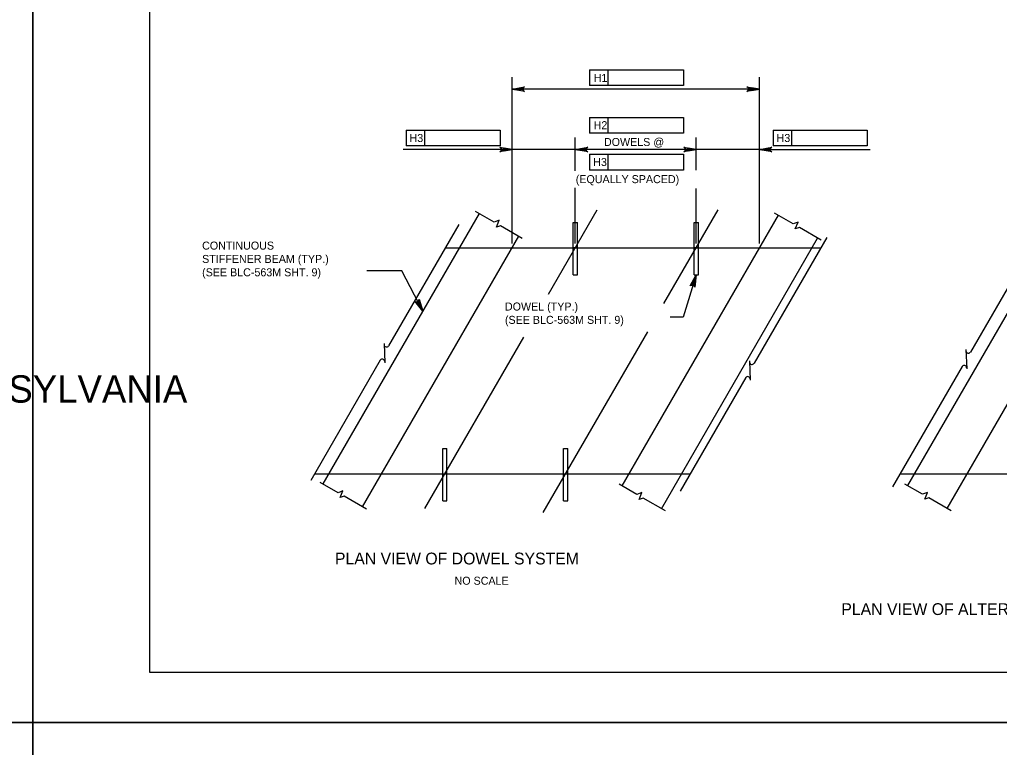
# Model space of a CAD drawing. Extents: x -8 to 75, y -110 to 0.
# Drawn here: x 33.8 to 48.5, y -22.38 to -11.47 of the extents above; entities that cross this region are included whole.
import ezdxf

# ---------------------------------------------------------------- set-up
doc = ezdxf.new("R2010")
doc.units = 0
for name, color, linetype in [('1', 7, 'Continuous'), ('2', 7, 'Continuous'), ('3', 7, 'Continuous'), ('4', 7, 'Continuous'), ('62', 7, 'Continuous'), ('63', 7, 'Continuous')]:
    doc.layers.add(name, color=color, linetype=linetype)

# ---------------------------------------------------------------- blocks, each defined once
blk = doc.blocks.new('D')
at = {"layer": '3'}
for p, q in [((-0.324, 0.383), (-0.383, 0.324)), ((0.349, -0.408), (-0.383, 0.324)), ((0.408, -0.349), (-0.324, 0.383)), ((0.408, -0.349), (0.349, -0.408))]:
    blk.add_line(p, q, dxfattribs=at)

msp = doc.modelspace()

# ---------------------------------------------------------------- linework, layer by layer
at = {"layer": '1'}
msp.add_lwpolyline([(35.75, -21.25), (67.25, -21.25), (67.25, -0.75), (35.75, -0.75)], close=True, dxfattribs=at)
at = {"layer": '2'}
for p, q in [((40.186, -14.886), (45.82, -14.886)), ((38.228, -18.275), (43.861, -18.275)), ((47.01, -18.275), (54.292, -18.275))]:
    msp.add_line(p, q, dxfattribs=at)
at = {"layer": '3'}
for p, q in [((40.697, -14.373), (38.354, -18.427)), ((40.923, -14.503), (40.643, -14.341)), ((41.735, -15.584), (42.467, -14.318)), ((45.18, -14.399), (42.837, -18.454)), ((43.468, -15.721), (44.28, -14.318)), ((45.407, -14.53), (45.126, -14.368)), ((49.465, -14.397), (47.122, -18.451)), ((40.389, -14.536), (39.337, -16.355)), ((40.995, -14.474), (40.923, -14.503)), ((40.955, -14.578), (40.995, -14.474)), ((45.479, -14.501), (45.407, -14.53)), ((45.438, -14.605), (45.479, -14.501)), ((41.017, -14.558), (40.955, -14.578)), ((41.343, -14.746), (41.017, -14.558)), ((45.5, -14.585), (45.438, -14.605)), ((45.827, -14.773), (45.5, -14.585)), ((49.117, -14.629), (48.065, -16.449)), ((38.947, -18.77), (41.29, -14.715)), ((43.43, -18.797), (45.773, -14.742)), ((45.91, -14.731), (44.819, -16.618)), ((47.715, -18.794), (50.058, -14.74)), ((42.17, -14.886), (42.107, -14.886)), ((43.983, -14.886), (43.92, -14.886)), ((41.657, -18.856), (43.224, -16.145)), ((39.881, -18.793), (41.365, -16.225)), ((39.269, -16.319), (39.28, -16.61)), ((47.997, -16.412), (48.008, -16.703)), ((39.213, -16.571), (38.171, -18.374)), ((44.751, -16.581), (44.761, -16.872)), ((47.941, -16.664), (46.898, -18.468)), ((44.695, -16.833), (43.711, -18.535)), ((38.58, -18.558), (38.312, -18.403)), ((43.063, -18.585), (42.796, -18.43)), ((47.348, -18.582), (47.081, -18.428)), ((38.652, -18.528), (38.58, -18.558)), ((38.611, -18.632), (38.652, -18.528)), ((38.674, -18.612), (38.611, -18.632)), ((39.006, -18.804), (38.674, -18.612)), ((43.135, -18.555), (43.063, -18.585)), ((43.095, -18.659), (43.135, -18.555)), ((43.157, -18.639), (43.095, -18.659)), ((43.49, -18.831), (43.157, -18.639)), ((47.42, -18.553), (47.348, -18.582)), ((47.38, -18.657), (47.42, -18.553)), ((47.442, -18.637), (47.38, -18.657)), ((47.775, -18.829), (47.442, -18.637))]:
    msp.add_line(p, q, dxfattribs=at)
for centre, start, end in [((39.306, -16.337), 179.9708, 329.9708), ((48.034, -16.431), 179.9708, 329.9708), ((39.243, -16.592), 2.1036, 144.6422), ((44.788, -16.599), 179.9708, 329.9708), ((47.971, -16.685), 2.1036, 144.6422), ((44.724, -16.854), 2.1036, 144.6422)]:
    msp.add_arc(centre, 0.0364, start, end, dxfattribs=at)
at = {"layer": '4'}
for p, q in [((41.191, -14.761), (41.191, -12.327)), ((42.349, -12.218), (43.761, -12.218)), ((42.349, -12.218), (42.349, -12.454)), ((42.625, -12.218), (42.625, -12.454)), ((43.761, -12.218), (43.761, -12.454)), ((44.899, -14.761), (44.899, -12.327)), ((43.761, -12.454), (42.349, -12.454)), ((44.899, -12.507), (41.191, -12.507)), ((42.349, -12.933), (42.349, -13.169)), ((42.349, -12.933), (43.761, -12.933)), ((42.625, -12.933), (42.625, -13.169)), ((43.761, -12.933), (43.761, -13.169)), ((39.599, -13.125), (41.011, -13.125)), ((39.599, -13.125), (39.599, -13.361)), ((39.874, -13.125), (39.874, -13.361)), ((41.011, -13.125), (41.011, -13.361)), ((43.761, -13.169), (42.349, -13.169)), ((45.104, -13.125), (46.516, -13.125)), ((45.104, -13.125), (45.104, -13.361)), ((45.379, -13.125), (45.379, -13.361)), ((46.516, -13.125), (46.516, -13.361)), ((41.011, -13.361), (39.599, -13.361)), ((41.191, -14.824), (41.191, -13.236)), ((42.138, -13.732), (42.138, -13.236)), ((43.951, -13.724), (43.951, -13.236)), ((44.899, -14.824), (44.899, -13.236)), ((46.516, -13.361), (45.104, -13.361)), ((41.071, -13.416), (39.556, -13.416)), ((42.138, -13.416), (41.19, -13.416)), ((43.831, -13.416), (42.258, -13.416)), ((42.349, -13.484), (43.761, -13.484)), ((42.349, -13.484), (42.349, -13.721)), ((42.625, -13.484), (42.625, -13.721)), ((43.831, -13.416), (43.711, -13.416)), ((43.761, -13.484), (43.761, -13.721)), ((44.899, -13.416), (43.951, -13.416)), ((45.019, -13.416), (46.562, -13.416)), ((43.761, -13.721), (42.349, -13.721)), ((42.138, -14.824), (42.138, -13.986)), ((43.951, -14.824), (43.951, -13.997)), ((39.535, -15.231), (39.011, -15.231)), ((43.757, -15.927), (43.563, -15.927))]:
    msp.add_line(p, q, dxfattribs=at)
for points in [[(41.191, -12.507), (41.378, -12.472), (41.363, -12.482), (41.356, -12.495), (41.354, -12.507), (41.356, -12.52), (41.363, -12.532), (41.378, -12.542), (41.191, -12.507), (41.363, -12.532), (41.356, -12.52), (41.191, -12.507), (41.354, -12.507), (41.356, -12.495), (41.191, -12.507), (41.363, -12.482)], [(44.899, -12.507), (44.712, -12.542), (44.727, -12.532), (44.734, -12.52), (44.736, -12.507), (44.734, -12.495), (44.727, -12.482), (44.712, -12.472), (44.899, -12.507), (44.727, -12.482), (44.734, -12.495), (44.899, -12.507), (44.736, -12.507), (44.734, -12.52), (44.899, -12.507), (44.727, -12.532)], [(41.191, -13.416), (41.005, -13.45), (41.019, -13.441), (41.026, -13.428), (41.029, -13.416), (41.026, -13.403), (41.019, -13.391), (41.005, -13.381), (41.191, -13.416), (41.019, -13.391), (41.026, -13.403), (41.191, -13.416), (41.029, -13.416), (41.026, -13.428), (41.191, -13.416), (41.019, -13.441)], [(42.138, -13.416), (42.325, -13.381), (42.31, -13.391), (42.303, -13.403), (42.301, -13.416), (42.303, -13.428), (42.31, -13.441), (42.325, -13.45), (42.138, -13.416), (42.31, -13.441), (42.303, -13.428), (42.138, -13.416), (42.301, -13.416), (42.303, -13.403), (42.138, -13.416), (42.31, -13.391)], [(43.951, -13.416), (43.764, -13.45), (43.779, -13.441), (43.786, -13.428), (43.788, -13.416), (43.786, -13.403), (43.779, -13.391), (43.764, -13.381), (43.951, -13.416), (43.779, -13.391), (43.786, -13.403), (43.951, -13.416), (43.788, -13.416), (43.786, -13.428), (43.951, -13.416), (43.779, -13.441)], [(44.899, -13.416), (45.085, -13.381), (45.071, -13.391), (45.063, -13.403), (45.061, -13.416), (45.063, -13.428), (45.071, -13.441), (45.085, -13.45), (44.899, -13.416), (45.071, -13.441), (45.063, -13.428), (44.899, -13.416), (45.061, -13.416), (45.063, -13.403), (44.899, -13.416), (45.071, -13.391)], [(39.85, -15.839), (39.535, -15.231)], [(43.951, -15.291), (43.757, -15.927)], [(43.951, -15.291), (43.93, -15.479), (43.925, -15.463), (43.915, -15.452), (43.904, -15.446), (43.891, -15.445), (43.877, -15.448), (43.863, -15.459), (43.951, -15.291), (43.877, -15.448), (43.891, -15.445), (43.951, -15.291), (43.904, -15.446), (43.915, -15.452), (43.951, -15.291), (43.925, -15.463)], [(39.85, -15.839), (39.733, -15.689), (39.748, -15.697), (39.763, -15.698), (39.775, -15.694), (39.785, -15.687), (39.793, -15.674), (39.795, -15.657), (39.85, -15.839), (39.793, -15.674), (39.785, -15.687), (39.85, -15.839), (39.775, -15.694), (39.763, -15.698), (39.85, -15.839), (39.748, -15.697)]]:
    msp.add_lwpolyline(points, dxfattribs=at)
for points in [[(41.311, -12.487), (41.311, -12.527), (41.191, -12.507)], [(44.779, -12.487), (44.779, -12.527), (44.899, -12.507)], [(41.071, -13.396), (41.071, -13.436), (41.191, -13.416)], [(42.258, -13.396), (42.258, -13.436), (42.138, -13.416)], [(43.831, -13.396), (43.831, -13.436), (43.951, -13.416)], [(45.019, -13.396), (45.019, -13.436), (44.899, -13.416)], [(43.951, -15.291), (43.906, -15.403), (43.925, -15.409)], [(39.85, -15.839), (39.803, -15.727), (39.785, -15.737)]]:
    msp.add_lwpolyline(points, close=True, dxfattribs=at)
at = {"layer": '62'}
msp.add_line((34, -22), (34, -22), dxfattribs=at)
at = {"layer": '63'}
for points in [[(0, -22), (34, -22), (34, 0), (0, 0)], [(34, -22), (68, -22), (68, 0), (34, 0)], [(0, -44), (34, -44), (34, -22), (0, -22)], [(34, -44), (68, -44), (68, -22), (34, -22)]]:
    msp.add_lwpolyline(points, close=True, dxfattribs=at)

# ---------------------------------------------------------------- block references
at = {"layer": '4', "xscale": 0.7559417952, "yscale": -0.7559417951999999, "rotation": -135.00004849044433}
for p in [(42.139, -14.886), (43.952, -14.886), (40.181, -18.275), (41.993, -18.275)]:
    msp.add_blockref('D', p, dxfattribs=at)

# ---------------------------------------------------------------- texts
at = {"layer": '1'}
msp.add_text('COMMONWEALTH OF PENNSYLVANIA', height=0.41038, dxfattribs=at).set_placement((26.196, -17.208))
at = {"layer": '4'}
for s, height, p in [('H1', 0.12, (42.414, -12.4)), ('H2', 0.12, (42.413, -13.109)), ('H3', 0.12, (39.652, -13.301)), ('H3', 0.12, (45.157, -13.301)), ('DOWELS @', 0.12, (42.568, -13.361)), ('H3', 0.12, (42.407, -13.661)), ('(EQUALLY SPACED)', 0.12, (42.145, -13.918)), ('CONTINUOUS', 0.12, (36.541, -14.914)), ('STIFFENER BEAM (TYP.)', 0.12, (36.541, -15.114)), ('(SEE BLC-563M SHT. 9)', 0.12, (36.541, -15.314)), ('DOWEL (TYP.)', 0.12, (41.083, -15.827)), ('(SEE BLC-563M SHT. 9)', 0.12, (41.083, -16.027)), ('PLAN VIEW OF DOWEL SYSTEM', 0.17717, (38.533, -19.633)), ('NO SCALE', 0.12, (40.327, -19.937)), ('PLAN VIEW OF ALTERNATE INTERMEDIATE STIFFENER BEAM SYSTEM', 0.17717, (46.128, -20.391))]:
    msp.add_text(s, height=height, dxfattribs=at).set_placement(p)

doc.saveas('drawing.dxf')
